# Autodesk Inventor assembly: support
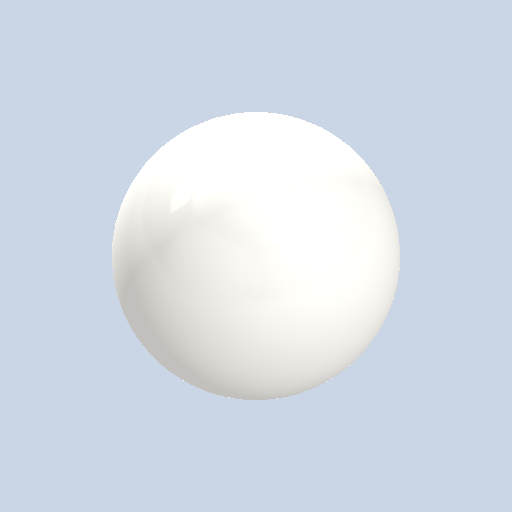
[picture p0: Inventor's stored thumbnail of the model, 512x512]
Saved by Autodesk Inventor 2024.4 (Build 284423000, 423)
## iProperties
Created: 2025-07
Part Number: support
Document SubType Name: Assembly
Designer: AdminForWorker
Title: support v1
Author: AdminForWorker
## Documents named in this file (2)
- c:\worker\convert-fusion-r03-cosv3\tmp\job-1\5\temp\files\c2717cec-cd30-4e2b-a2e5-52afbc4802da\support v1_3.iam
- c:\worker\convert-fusion-r03-cosv3\tmp\job-1\5\temp\files\c2717cec-cd30-4e2b-a2e5-52afbc4802da\Component1.ipt
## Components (1 placed, 1 different names)
1. Component1:1
